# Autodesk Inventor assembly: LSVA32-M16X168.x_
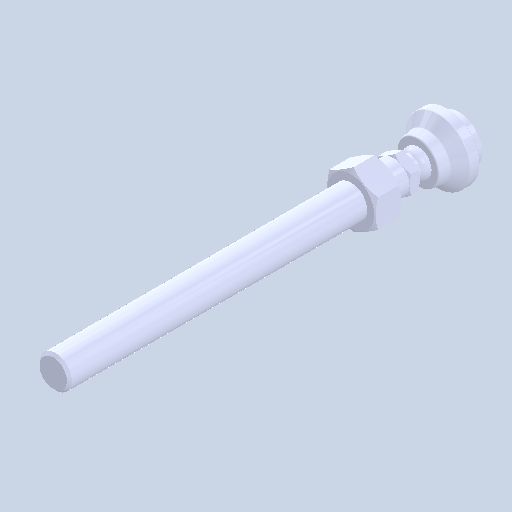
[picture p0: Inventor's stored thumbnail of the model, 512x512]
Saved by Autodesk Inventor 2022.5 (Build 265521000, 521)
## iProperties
Created: 2024-08
Part Number: LSVA32-M16X168.x_
Document SubType Name: Assembly
Designer: ImaoCorp
Author: ImaoCorp
Sending System: SOLIDWORKS 2022-2022290
MC: AMD64
MC_MODEL: Intel64 Family 6 Model 60 Stepping 3, GenuineIntel
OS: Windows_NT
FRU: Parasolid Version 33.1, build 260,  4-25-2022
FORMAT: text
GUISE: transmit
KEY: FILELSVA32-M16X168.x_t
DATE: Fri Aug 23 16:06:54 2024
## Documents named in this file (4)
- X:\14_SW2022-Inv2022\06_2024-10新製品(SME)\ELS_データ\l\lsva32-m16x168\LSVA32-M16X168.x_.iam
- X:\14_SW2022-Inv2022\06_2024-10新製品(SME)\ELS_データ\l\lsva32-m16x168\LSVA32-M16X168_01.ipt
- X:\14_SW2022-Inv2022\06_2024-10新製品(SME)\ELS_データ\l\lsva32-m16x168\LSVA32-M16X168_02.ipt
- X:\14_SW2022-Inv2022\06_2024-10新製品(SME)\ELS_データ\l\lsva32-m16x168\LSVA32-M16X168_03.ipt
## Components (3 placed, 3 different names)
1. LSVA32-M16X168_01
2. LSVA32-M16X168_02
3. LSVA32-M16X168_03
